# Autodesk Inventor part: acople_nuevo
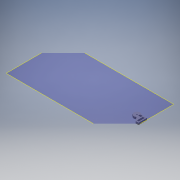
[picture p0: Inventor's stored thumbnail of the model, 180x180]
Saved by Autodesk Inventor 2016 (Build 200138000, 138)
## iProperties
Created: 2017-06
Part Number: acople_nuevo
Material: Generic
Document SubType Name: Modeling
Designer: laboratorioesan
Density: 1 g/cm^3
Appearance: Default
Author: laboratorioesan
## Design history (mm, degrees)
workplane "Work Plane1"
sketch "Sketch1"
  geometry: L1 (428.5, -285.317)-(447, -285.317) reference; L2 (447, -285.317)-(447, -345.317) reference; L3 (447, -345.317)-(428.5, -345.317) reference; L4 (428.5, -345.317)-(428.5, -285.317) reference; L5 (-447, -345.317)-(-447, -285.317) reference; L6 (-447, -285.317)-(-428.5, -285.317) reference; L7 (-428.5, -285.317)-(-428.5, -345.317) reference; L8 (-428.5, -345.317)-(-447, -345.317) reference; L9 (-480.59, -216.985)-(-467, -261.342) reference; L10 (-467, -261.342)-(-467, -375.317) reference; L11 (-467, -375.317)-(-370, -375.317) reference; L12 (-370, -52.817)-(-370, -375.317) reference; L13 (310, 7.183)-(-310, 7.183) reference; L14 (370, -52.817)-(370, -375.317) reference; L15 (370, -375.317)-(467, -375.317) reference; L16 (467, -375.317)-(467, -261.342) reference; L17 (467, -261.342)-(480.59, -216.985) reference; L18 (495.188, 14.837)-(477.824, 115.072) reference; L19 (-427.975, 141.679)-(427.975, 141.679) reference; L20 (-477.824, 115.072)-(-495.188, 14.837) reference; L21 (120, 85.683)-(120, 104.183) reference; L22 (120, 104.183)-(180, 104.183) reference; L23 (180, 104.183)-(180, 85.683) reference; L24 (180, 85.683)-(120, 85.683) reference; L25 (-370, 104.183)-(-370, 85.683) reference; L26 (-370, 85.683)-(-430, 85.683) reference; L27 (-430, 85.683)-(-430, 104.183) reference; L28 (-430, 104.183)-(-370, 104.183) reference; L29 (-180, 85.683)-(-180, 104.183) reference; L30 (-180, 104.183)-(-120, 104.183) reference; L31 (-120, 104.183)-(-120, 85.683) reference; L32 (-120, 85.683)-(-180, 85.683) reference; L33 (370, 85.683)-(370, 104.183) reference; L34 (370, 104.183)-(430, 104.183) reference; L35 (430, 104.183)-(430, 85.683) reference; L36 (430, 85.683)-(370, 85.683) reference; L37 (-400, 55.683)-(-400, 37.183) reference; L38 (-400, 37.183)-(-460, 37.183) reference; L39 (-460, 37.183)-(-460, 55.683) reference; L40 (-460, 55.683)-(-400, 55.683) reference; L41 (-190, 55.683)-(-190, 37.183) reference; L42 (-190, 37.183)-(-250, 37.183) reference; L43 (-250, 37.183)-(-250, 55.683) reference; L44 (-250, 55.683)-(-190, 55.683) reference; L45 (30, 55.683)-(30, 37.183) reference; L46 (30, 37.183)-(-30, 37.183) reference; L47 (-30, 37.183)-(-30, 55.683) reference; L48 (-30, 55.683)-(30, 55.683) reference; L49 (460, 55.683)-(460, 37.183) reference; L50 (460, 37.183)-(400, 37.183) reference; L51 (400, 37.183)-(400, 55.683) reference; L52 (400, 55.683)-(460, 55.683) reference; L53 (250, 55.683)-(250, 37.183) reference; L54 (250, 37.183)-(190, 37.183) reference; L55 (190, 37.183)-(190, 55.683) reference; L56 (190, 55.683)-(250, 55.683) reference; L57 (-526, -95.317)-(-526, -155.317); L58 (-526, -155.317)-(-507.5, -155.317); L59 (-507.5, -155.317)-(-507.5, -95.317); L60 (-507.5, -95.317)-(-526, -95.317); L61 (-497.5, -88.479)-(-497.5, -106.979); L62 (-497.5, -106.979)-(-472.5, -106.979); L63 (-472.5, -106.979)-(-472.5, -88.479); L64 (-472.5, -88.479)-(-497.5, -88.479)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; C1 r 5.25 at (-456, -102.817) reference; C2 r 5.25 at (456, -102.817) reference; C3 r 5.25 at (-456, -102.817); A1 r 500 centre (-2.526, -70.511) between (-495.188, 14.837) and (-480.59, -216.985) reference; A2 r 60 centre (-310, -52.817) between (-310, 7.183) and (-370, -52.817) reference; A3 r 60 centre (310, -52.817) between (370, -52.817) and (310, 7.183) reference; A4 r 500 centre (2.526, -70.511) between (480.59, -216.985) and (495.188, 14.837) reference; A5 r 60 centre (427.975, 81.679) between (477.824, 115.072) and (427.975, 141.679) reference; A6 r 60 centre (-427.975, 81.679) between (-427.975, 141.679) and (-477.824, 115.072) reference; A7 r 32.5 centre (-456, -102.817) between (-475.816, -128.578) and (-481.617, -82.817); 1 further point
  constraints: 24 end point, 2 centre point, 2 point on circle
extrude "Extrusion1" new body sketch "Sketch1" distance "d0" = 20.5; taper "d1" = 0 deg
body "Solid1"
node "Reference1"
